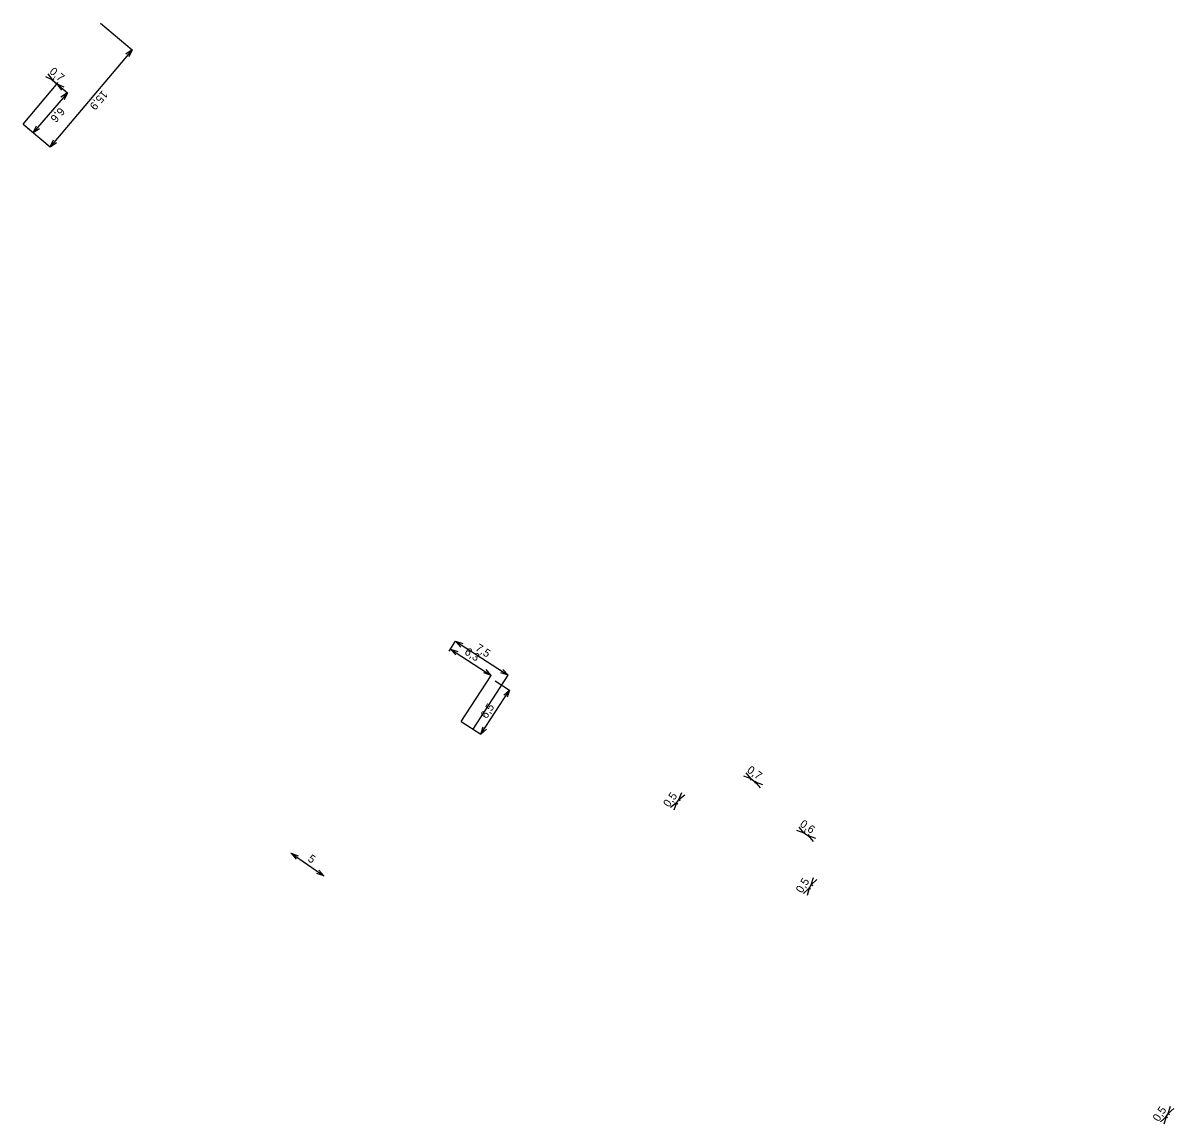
# Model space of a CAD drawing. Extents: x -742845 to -742557, y -1054636 to -1054445.
# Drawn here: x -742700.4 to -742556.6, y -1054582.4 to -1054444.8 of the extents above; entities that cross this region are included whole.
import ezdxf

# ---------------------------------------------------------------- set-up
doc = ezdxf.new("R2010")
doc.units = 0
doc.layers.add('Kota_NN', color=7, linetype='Continuous')
doc.layers.add('Kota_VN', color=7, linetype='Continuous')

msp = doc.modelspace()

# ---------------------------------------------------------------- linework, layer by layer
at = {"layer": 'Kota_NN'}
for p, q in [((-742647.17, -1054523.29), (-742646.38, -1054522.07)), ((-742646.38, -1054522.07), (-742639.83, -1054526.32)), ((-742646.38, -1054522.07), (-742645.47, -1054522.37)), ((-742646.38, -1054522.07), (-742645.74, -1054522.79)), ((-742647.17, -1054523.29), (-742647.01, -1054523.04)), ((-742647.01, -1054523.04), (-742641.93, -1054526.33)), ((-742647.01, -1054523.04), (-742646.09, -1054523.33)), ((-742647.01, -1054523.04), (-742646.36, -1054523.75)), ((-742641.93, -1054526.33), (-742642.57, -1054525.61)), ((-742639.83, -1054526.32), (-742640.48, -1054525.6)), ((-742645.68, -1054532.11), (-742641.93, -1054526.33)), ((-742644.2, -1054533.06), (-742639.83, -1054526.32)), ((-742641.93, -1054526.33), (-742642.84, -1054526.03)), ((-742641.44, -1054527), (-742639.66, -1054528.16)), ((-742639.83, -1054526.32), (-742640.75, -1054526.02)), ((-742643.24, -1054533.69), (-742639.66, -1054528.16)), ((-742639.66, -1054528.16), (-742640.37, -1054528.8)), ((-742639.66, -1054528.16), (-742639.95, -1054529.07)), ((-742645.68, -1054532.11), (-742643.24, -1054533.69)), ((-742643.24, -1054533.69), (-742642.95, -1054532.78)), ((-742643.24, -1054533.69), (-742642.53, -1054533.05)), ((-742609.48, -1054539.26), (-742610.09, -1054538.52)), ((-742609.48, -1054539.26), (-742610.38, -1054538.93)), ((-742609.64, -1054539.14), (-742608.78, -1054539.75)), ((-742609.43, -1054539.2), (-742609.59, -1054539.42)), ((-742608.9, -1054539.57), (-742609.06, -1054539.8)), ((-742608.95, -1054539.63), (-742608.04, -1054539.96)), ((-742608.95, -1054539.63), (-742608.33, -1054540.37)), ((-742618.49, -1054541.86), (-742618.14, -1054540.96)), ((-742618.49, -1054541.86), (-742617.74, -1054541.26)), ((-742618.78, -1054542.26), (-742619.53, -1054542.86)), ((-742618.78, -1054542.26), (-742619.13, -1054543.16)), ((-742618.9, -1054542.42), (-742618.37, -1054541.7)), ((-742618.84, -1054542.22), (-742618.62, -1054542.38)), ((-742618.55, -1054541.81), (-742618.33, -1054541.98)), ((-742602.84, -1054546.03), (-742603.75, -1054545.71)), ((-742602.84, -1054546.03), (-742603.47, -1054545.3)), ((-742602.85, -1054546.04), (-742602.73, -1054545.86)), ((-742603.01, -1054545.92), (-742602.18, -1054546.47)), ((-742602.35, -1054546.38), (-742602.23, -1054546.2)), ((-742602.34, -1054546.36), (-742601.44, -1054546.68)), ((-742602.34, -1054546.36), (-742601.71, -1054547.09)), ((-742666.96, -1054548.59), (-742666.94, -1054548.56)), ((-742666.94, -1054548.56), (-742662.83, -1054551.39)), ((-742666.94, -1054548.56), (-742666.04, -1054548.88)), ((-742666.94, -1054548.56), (-742666.32, -1054549.29)), ((-742662.83, -1054551.39), (-742663.73, -1054551.07)), ((-742662.83, -1054551.39), (-742663.45, -1054550.66)), ((-742662.84, -1054551.42), (-742662.83, -1054551.39)), ((-742601.95, -1054552.49), (-742601.67, -1054551.57)), ((-742602.22, -1054552.92), (-742602.92, -1054553.57)), ((-742602.22, -1054552.92), (-742602.49, -1054553.84)), ((-742602.32, -1054553.09), (-742601.85, -1054552.32)), ((-742602.27, -1054552.88), (-742602.05, -1054553.02)), ((-742602.01, -1054552.46), (-742601.78, -1054552.59)), ((-742601.95, -1054552.49), (-742601.25, -1054551.83)), ((-742557.37, -1054581.09), (-742557.07, -1054580.18)), ((-742557.62, -1054581.48), (-742558.34, -1054582.11)), ((-742557.62, -1054581.48), (-742557.92, -1054582.39)), ((-742557.73, -1054581.64), (-742557.26, -1054580.92)), ((-742557.64, -1054581.46), (-742557.45, -1054581.58)), ((-742557.39, -1054581.07), (-742557.2, -1054581.2)), ((-742557.37, -1054581.09), (-742556.65, -1054580.45))]:
    msp.add_line(p, q, dxfattribs=at)
at = {"layer": 'Kota_VN'}
for p, q in [((-742690.76, -1054444.82), (-742686.8, -1054448.16)), ((-742686.8, -1054448.16), (-742697.03, -1054460.3)), ((-742686.8, -1054448.16), (-742687.59, -1054448.71)), ((-742686.8, -1054448.16), (-742687.21, -1054449.03)), ((-742700.42, -1054457.44), (-742696.05, -1054452.25)), ((-742696.71, -1054451.95), (-742697.58, -1054451.54)), ((-742696.71, -1054451.95), (-742697.26, -1054451.16)), ((-742696.86, -1054451.82), (-742696.02, -1054452.53)), ((-742696.72, -1054451.97), (-742696.58, -1054451.8)), ((-742696.72, -1054451.97), (-742694.88, -1054453.55)), ((-742696.18, -1054452.4), (-742695.31, -1054452.81)), ((-742696.18, -1054452.4), (-742695.63, -1054453.19)), ((-742694.88, -1054453.55), (-742699.16, -1054458.52)), ((-742694.88, -1054453.55), (-742695.68, -1054454.09)), ((-742694.88, -1054453.55), (-742695.3, -1054454.41)), ((-742700.42, -1054457.44), (-742697.03, -1054460.3)), ((-742700.42, -1054457.44), (-742699.16, -1054458.52)), ((-742699.16, -1054458.52), (-742698.74, -1054457.66)), ((-742699.16, -1054458.52), (-742698.37, -1054457.98)), ((-742697.03, -1054460.3), (-742696.62, -1054459.43)), ((-742697.03, -1054460.3), (-742696.24, -1054459.75))]:
    msp.add_line(p, q, dxfattribs=at)

# ---------------------------------------------------------------- texts
at = {"layer": 'Kota_NN'}
for s, rotation, p in [('7,5', 327.0517, (-742644, -1054523.14)), ('6,3', 327.0518, (-742645.36, -1054523.62)), ('6,5', 57.0514, (-742642.51, -1054531.82)), ('0,7', 324.8823, (-742610.07, -1054538.36)), ('0,5', 53.7383, (-742619.74, -1054542.89)), ('0,6', 326.0552, (-742603.47, -1054545.12)), ('5', 325.4531, (-742664.93, -1054549.46)), ('0,5', 58.2732, (-742603.12, -1054553.62)), ('0,5', 56.7182, (-742558.56, -1054582.17))]:
    msp.add_text(s, height=1, rotation=rotation, dxfattribs=at).set_placement(p)
at = {"layer": 'Kota_VN'}
for s, rotation, p in [('0,7', 319.8897, (-742697.2, -1054451.02)), ('15,9', 229.8808, (-742690.49, -1054453.16)), ('6,6', 229.3143, (-742695.85, -1054455.29))]:
    msp.add_text(s, height=1, rotation=rotation, dxfattribs=at).set_placement(p)

doc.saveas('drawing.dxf')
